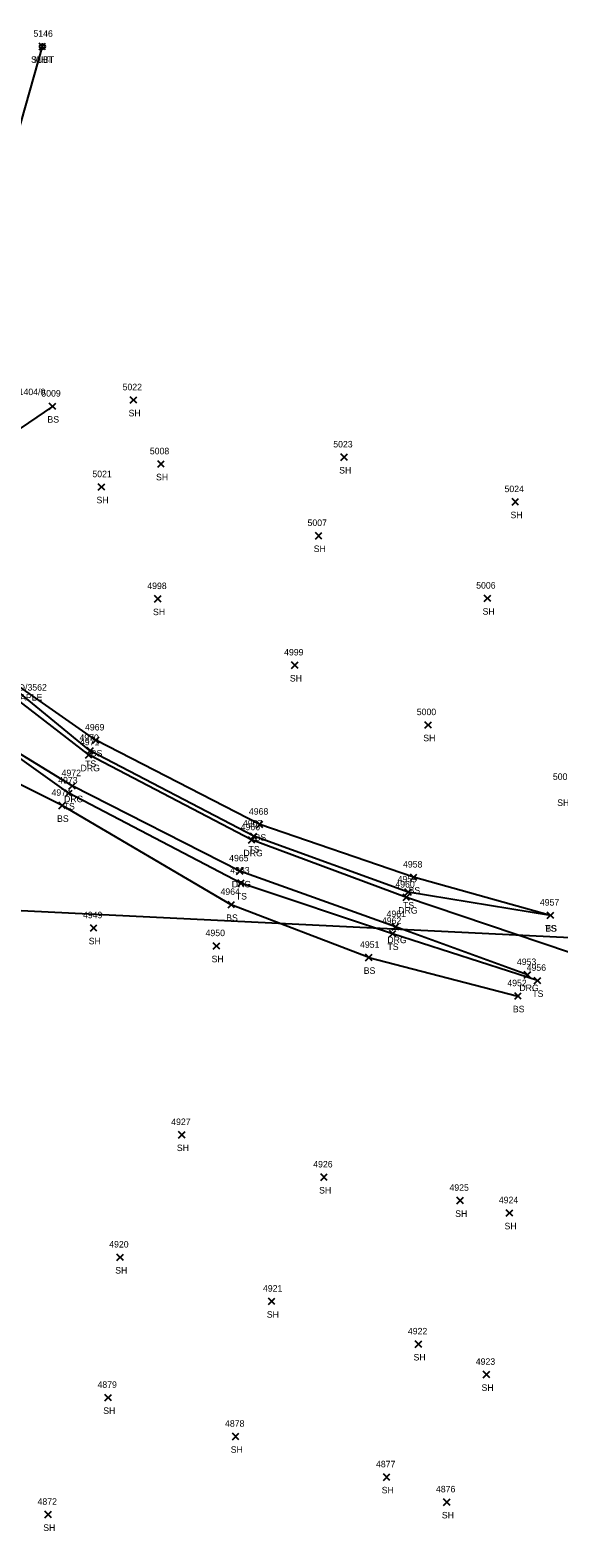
# Model space of a CAD drawing. Extents: x 1601151 to 1602912, y 499508 to 501770.
# Drawn here: x 1601569.7 to 1601732, y 501306.7 to 501769.6 of the extents above; entities that cross this region are included whole.
import ezdxf

# ---------------------------------------------------------------- set-up
doc = ezdxf.new("R2010")
doc.units = 0
for name, color, linetype in [('L_A', 7, 'Continuous'), ('L_C', 7, 'Continuous'), ('L_I', 7, 'Continuous'), ('L_TIC', 7, 'Continuous'), ('LELB', 7, 'Continuous'), ('R_A', 7, 'Continuous'), ('R_I', 7, 'Continuous'), ('R_TIC', 7, 'Continuous'), ('RDG', 7, 'Continuous'), ('S_C', 7, 'Continuous'), ('U_A', 7, 'Continuous'), ('U_I', 7, 'Continuous'), ('U_TIC', 7, 'Continuous'), ('UCO', 7, 'Continuous'), ('UT', 7, 'Continuous'), ('UTMH', 7, 'Continuous')]:
    doc.layers.add(name, color=color, linetype=linetype)

msp = doc.modelspace()

# ---------------------------------------------------------------- linework, layer by layer
at = {"layer": 'L_TIC'}
for points in [[(1601600.39, 501655.01), (1601602.39, 501657.01)], [(1601602.39, 501655.01), (1601600.39, 501657.01)], [(1601575.53, 501653.07), (1601577.53, 501655.07)], [(1601577.53, 501653.07), (1601575.53, 501655.07)], [(1601665.06, 501637.46), (1601667.06, 501639.46)], [(1601667.06, 501637.46), (1601665.06, 501639.46)], [(1601608.83, 501635.36), (1601610.83, 501637.36)], [(1601610.83, 501635.36), (1601608.83, 501637.36)], [(1601590.54, 501628.32), (1601592.54, 501630.32)], [(1601592.54, 501628.32), (1601590.54, 501630.32)], [(1601717.66, 501623.74), (1601719.66, 501625.74)], [(1601719.66, 501623.74), (1601717.66, 501625.74)], [(1601657.25, 501613.35), (1601659.25, 501615.35)], [(1601659.25, 501613.35), (1601657.25, 501615.35)], [(1601607.89, 501593.98), (1601609.89, 501595.98)], [(1601609.89, 501593.98), (1601607.89, 501595.98)], [(1601709.09, 501594.12), (1601711.09, 501596.12)], [(1601711.09, 501594.12), (1601709.09, 501596.12)], [(1601649.91, 501573.61), (1601651.91, 501575.61)], [(1601651.91, 501573.61), (1601649.91, 501575.61)], [(1601690.88, 501555.28), (1601692.88, 501557.28)], [(1601692.88, 501555.28), (1601690.88, 501557.28)], [(1601588.82, 501550.58), (1601590.82, 501552.58)], [(1601590.82, 501550.58), (1601588.82, 501552.58)], [(1601587.13, 501547.36), (1601589.13, 501549.36)], [(1601589.13, 501547.36), (1601587.13, 501549.36)], [(1601578.48, 501530.53), (1601580.48, 501532.53)], [(1601580.48, 501530.53), (1601578.48, 501532.53)], [(1601580.54, 501534.3), (1601582.54, 501536.3)], [(1601582.54, 501534.3), (1601580.54, 501536.3)], [(1601637.3, 501521.09), (1601639.3, 501523.09)], [(1601639.3, 501521.09), (1601637.3, 501523.09)], [(1601639.14, 501524.73), (1601641.14, 501526.73)], [(1601641.14, 501524.73), (1601639.14, 501526.73)], [(1601686.41, 501508.5), (1601688.41, 501510.5)], [(1601688.41, 501508.5), (1601686.41, 501510.5)], [(1601633.4, 501506.69), (1601635.4, 501508.69)], [(1601635.4, 501506.69), (1601633.4, 501508.69)], [(1601684.74, 501503.94), (1601686.74, 501505.94)], [(1601686.74, 501503.94), (1601684.74, 501505.94)], [(1601630.42, 501500.1), (1601632.42, 501502.1)], [(1601632.42, 501500.1), (1601630.42, 501502.1)], [(1601728.43, 501496.82), (1601730.43, 501498.82)], [(1601730.43, 501496.82), (1601728.43, 501498.82)], [(1601728.43, 501496.82), (1601730.43, 501498.82)], [(1601730.43, 501496.82), (1601728.43, 501498.82)], [(1601588.16, 501492.93), (1601590.16, 501494.93)], [(1601590.16, 501492.93), (1601588.16, 501494.93)], [(1601679.97, 501491.19), (1601681.97, 501493.19)], [(1601681.97, 501491.19), (1601679.97, 501493.19)], [(1601625.88, 501487.44), (1601627.88, 501489.44)], [(1601627.88, 501487.44), (1601625.88, 501489.44)], [(1601672.64, 501483.87), (1601674.64, 501485.87)], [(1601674.64, 501483.87), (1601672.64, 501485.87)], [(1601672.64, 501483.87), (1601674.64, 501485.87)], [(1601674.64, 501483.87), (1601672.64, 501485.87)], [(1601724.43, 501476.79), (1601726.43, 501478.79)], [(1601726.43, 501476.79), (1601724.43, 501478.79)], [(1601718.44, 501472.07), (1601720.44, 501474.07)], [(1601720.44, 501472.07), (1601718.44, 501474.07)], [(1601615.24, 501429.46), (1601617.24, 501431.46)], [(1601617.24, 501429.46), (1601615.24, 501431.46)], [(1601658.9, 501416.44), (1601660.9, 501418.44)], [(1601660.9, 501416.44), (1601658.9, 501418.44)], [(1601700.68, 501409.27), (1601702.68, 501411.27)], [(1601702.68, 501409.27), (1601700.68, 501411.27)], [(1601715.83, 501405.45), (1601717.83, 501407.45)], [(1601717.83, 501405.45), (1601715.83, 501407.45)], [(1601596.28, 501391.86), (1601598.28, 501393.86)], [(1601598.28, 501391.86), (1601596.28, 501393.86)], [(1601642.84, 501378.32), (1601644.84, 501380.32)], [(1601644.84, 501378.32), (1601642.84, 501380.32)], [(1601687.91, 501365.19), (1601689.91, 501367.19)], [(1601689.91, 501365.19), (1601687.91, 501367.19)], [(1601708.76, 501355.86), (1601710.76, 501357.86)], [(1601710.76, 501355.86), (1601708.76, 501357.86)], [(1601592.61, 501348.77), (1601594.61, 501350.77)], [(1601594.61, 501348.77), (1601592.61, 501350.77)], [(1601631.76, 501336.85), (1601633.76, 501338.85)], [(1601633.76, 501336.85), (1601631.76, 501338.85)], [(1601678.12, 501324.39), (1601680.12, 501326.39)], [(1601680.12, 501324.39), (1601678.12, 501326.39)], [(1601574.19, 501312.88), (1601576.19, 501314.88)], [(1601576.19, 501312.88), (1601574.19, 501314.88)], [(1601696.59, 501316.7), (1601698.59, 501318.7)], [(1601698.59, 501316.7), (1601696.59, 501318.7)]]:
    msp.add_lwpolyline(points, dxfattribs=at)
at = {"layer": 'LELB'}
for points in [[(1601576.53, 501654.07), (1601551.72, 501637.28), (1601544.25, 501620.77), (1601536.16, 501590.67)], [(1601729.43, 501497.82), (1601685.74, 501504.94), (1601638.3, 501522.09), (1601588.13, 501548.36), (1601550.78, 501578.83)], [(1601729.43, 501497.82), (1601687.41, 501509.5), (1601640.14, 501525.73), (1601589.82, 501551.58), (1601550.78, 501578.83)], [(1601725.43, 501477.79), (1601680.97, 501492.19), (1601634.4, 501507.69), (1601581.54, 501535.3), (1601553.07, 501555.64)], [(1601673.64, 501484.87), (1601631.42, 501501.1), (1601579.48, 501531.53), (1601544.7, 501548.89), (1601526.08, 501542.78), (1601522.81, 501541.12)], [(1601673.64, 501484.87), (1601719.44, 501473.07)]]:
    msp.add_lwpolyline(points, dxfattribs=at)
at = {"layer": 'R_TIC'}
for points in [[(1601586.64, 501546.05), (1601588.64, 501548.05)], [(1601588.64, 501546.05), (1601586.64, 501548.05)], [(1601581.57, 501536.55), (1601583.57, 501538.55)], [(1601583.57, 501536.55), (1601581.57, 501538.55)], [(1601636.66, 501519.96), (1601638.66, 501521.96)], [(1601638.66, 501519.96), (1601636.66, 501521.96)], [(1601633.07, 501510.4), (1601635.07, 501512.4)], [(1601635.07, 501510.4), (1601633.07, 501512.4)], [(1601684.19, 501502.35), (1601686.19, 501504.35)], [(1601686.19, 501502.35), (1601684.19, 501504.35)], [(1601680.84, 501493.29), (1601682.84, 501495.29)], [(1601682.84, 501493.29), (1601680.84, 501495.29)], [(1601721.39, 501478.57), (1601723.39, 501480.57)], [(1601723.39, 501478.57), (1601721.39, 501480.57)]]:
    msp.add_lwpolyline(points, dxfattribs=at)
at = {"layer": 'RDG'}
for points in [[(1601735.26, 501486.44), (1601685.19, 501503.35), (1601637.66, 501520.96), (1601587.64, 501547.05), (1601549.26, 501576.69), (1601539.36, 501585.43), (1601536.16, 501590.67), (1601533.36, 501599.4), (1601531.25, 501603.07)], [(1601722.39, 501479.57), (1601681.84, 501494.29), (1601634.07, 501511.4), (1601582.57, 501537.55), (1601553.07, 501555.64), (1601536.01, 501559.98), (1601527.74, 501556.44), (1601520.07, 501552.2)]]:
    msp.add_lwpolyline(points, dxfattribs=at)
at = {"layer": 'U_TIC'}
for points in [[(1601572.42, 501763.52), (1601574.42, 501765.52)], [(1601574.42, 501763.52), (1601572.42, 501765.52)]]:
    msp.add_lwpolyline(points, dxfattribs=at)
at = {"layer": 'UCO'}
msp.add_lwpolyline([(1601766.65, 501489.44), (1601471.02, 501503.9), (1601438.7, 501339.97), (1601411.28, 501184.01), (1601489.93, 500928.89)], dxfattribs=at)
at = {"layer": 'UT'}
msp.add_lwpolyline([(1601530.45, 501606.24), (1601540.73, 501649), (1601573.42, 501764.52)], dxfattribs=at)
at = {"layer": 'UTMH'}
for p, q in [((1601573.42, 501764.52), (1601573.42, 501764.52)), ((1601574.25, 501764.52), (1601574.25, 501764.52))]:
    msp.add_line(p, q, dxfattribs=at)
msp.add_circle((1601573.42, 501764.52), 0.833, dxfattribs=at)

# ---------------------------------------------------------------- texts
at = {"layer": 'L_A'}
for s, p in [('SH', (1601599.88, 501651.01)), ('BS', (1601574.97, 501649.07)), ('SH', (1601664.55, 501633.46)), ('SH', (1601608.32, 501631.36)), ('SH', (1601590.03, 501624.32)), ('SH', (1601717.15, 501619.74)), ('SH', (1601656.73, 501609.35)), ('SH', (1601607.38, 501589.98)), ('SH', (1601708.58, 501590.12)), ('SH', (1601649.4, 501569.61)), ('SH', (1601690.37, 501551.28)), ('BS', (1601588.26, 501546.58)), ('TS', (1601586.54, 501543.36)), ('TS', (1601579.95, 501530.3)), ('SH', (1601731.5, 501531.41)), ('BS', (1601577.92, 501526.53)), ('BS', (1601638.58, 501520.73)), ('TS', (1601636.71, 501517.09)), ('TS', (1601632.81, 501502.69)), ('BS', (1601685.85, 501504.5)), ('TS', (1601684.15, 501499.94)), ('BS', (1601629.86, 501496.1)), ('SH', (1601587.65, 501488.93)), ('TS', (1601727.84, 501492.82)), ('BS', (1601727.87, 501492.82)), ('TS', (1601679.38, 501487.19)), ('SH', (1601625.37, 501483.44)), ('BS', (1601672.08, 501479.87)), ('BS', (1601672.08, 501479.87)), ('TS', (1601723.84, 501472.79)), ('BS', (1601717.88, 501468.07)), ('SH', (1601614.72, 501425.46)), ('SH', (1601658.39, 501412.44)), ('SH', (1601700.17, 501405.27)), ('SH', (1601715.32, 501401.45)), ('SH', (1601595.77, 501387.86)), ('SH', (1601642.33, 501374.32)), ('SH', (1601687.39, 501361.19)), ('SH', (1601708.25, 501351.86)), ('SH', (1601592.1, 501344.77)), ('SH', (1601631.25, 501332.85)), ('SH', (1601677.61, 501320.39)), ('SH', (1601696.07, 501312.7)), ('SH', (1601573.68, 501308.88))]:
    msp.add_text(s, height=2, dxfattribs=at).set_placement(p)
at = {"layer": 'L_C'}
msp.add_text('10"MAPLE', height=2, dxfattribs=at).set_placement((1601560.4, 501563.77))
at = {"layer": 'L_I'}
for s, p in [('5009', (1601573.1, 501657.07)), ('5022', (1601598.05, 501659.01)), ('5023', (1601662.73, 501641.46)), ('5008', (1601606.41, 501639.36)), ('5021', (1601588.77, 501632.32)), ('5024', (1601715.32, 501627.74)), ('5007', (1601654.83, 501617.35)), ('4998', (1601605.63, 501597.98)), ('5006', (1601706.62, 501598.12)), ('4999', (1601647.64, 501577.61)), ('5000', (1601688.38, 501559.28)), ('4969', (1601586.5, 501554.58)), ('4970', (1601584.79, 501551.36)), ('5001', (1601730.17, 501539.41)), ('4973', (1601578.28, 501538.3)), ('4974', (1601576.22, 501534.53)), ('4968', (1601636.83, 501528.73)), ('4967', (1601634.99, 501525.09)), ('4958', (1601684.15, 501512.5)), ('4963', (1601631.09, 501510.69)), ('4959', (1601682.48, 501507.94)), ('4964', (1601628.11, 501504.1)), ('4957', (1601726.17, 501500.82)), ('4957', (1601726.17, 501500.82)), ('4949', (1601585.89, 501496.93)), ('4962', (1601677.67, 501495.19)), ('4950', (1601623.53, 501491.44)), ('4951', (1601670.95, 501487.87)), ('4951', (1601670.95, 501487.87)), ('4956', (1601722.12, 501480.79)), ('4952', (1601716.18, 501476.07)), ('4927', (1601612.98, 501433.46)), ('4926', (1601656.58, 501420.44)), ('4925', (1601698.42, 501413.27)), ('4924', (1601713.57, 501409.45)), ('4920', (1601593.94, 501395.86)), ('4921', (1601641.15, 501382.32)), ('4922', (1601685.65, 501369.19)), ('4923', (1601706.5, 501359.86)), ('4879', (1601590.34, 501352.77)), ('4878', (1601629.5, 501340.85)), ('4877', (1601675.86, 501328.39)), ('4876', (1601694.27, 501320.7)), ('4872', (1601571.93, 501316.88))]:
    msp.add_text(s, height=2, dxfattribs=at).set_placement(p)
at = {"layer": 'R_A'}
for p in [(1601585.13, 501542.05), (1601580.06, 501532.55), (1601635.15, 501515.96), (1601631.56, 501506.4), (1601682.68, 501498.35), (1601679.33, 501489.29), (1601719.87, 501474.57)]:
    msp.add_text('DRG', height=2, dxfattribs=at).set_placement(p)
at = {"layer": 'R_I'}
for s, p in [('4971', (1601584.95, 501550.05)), ('4972', (1601579.31, 501540.55)), ('4966', (1601634.3, 501523.96)), ('4965', (1601630.76, 501514.4)), ('4960', (1601681.8, 501506.35)), ('4961', (1601679.1, 501497.29)), ('4953', (1601719.13, 501482.57))]:
    msp.add_text(s, height=2, dxfattribs=at).set_placement(p)
at = {"layer": 'S_C'}
for s, p in [('S CURVE AHEAD 35MPH-0120/1404/0', (1601527.04, 501657.52)), ('TYSON JUSTIN ROAD/3562', (1601540.3, 501566.82))]:
    msp.add_text(s, height=2, dxfattribs=at).set_placement(p)
at = {"layer": 'U_A'}
for s, p in [('SUBT', (1601569.92, 501759.52)), ('MHT', (1601570.8, 501759.52))]:
    msp.add_text(s, height=2, dxfattribs=at).set_placement(p)
at = {"layer": 'U_I'}
msp.add_text('5146', height=2, dxfattribs=at).set_placement((1601570.67, 501767.52))
msp.add_text('5146', height=2, dxfattribs=at).set_placement((1601570.67, 501767.52))

doc.saveas('drawing.dxf')
